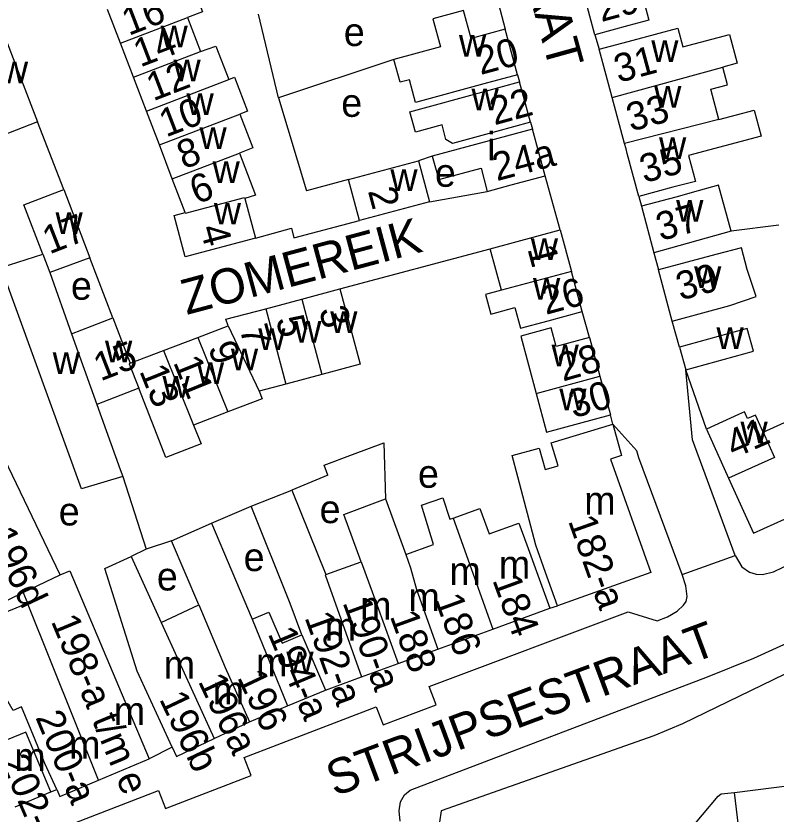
# Model space of a CAD drawing. Extents: x 159261 to 160849, y 382514 to 384534.
# Drawn here: x 159592.3 to 159700.2, y 383560.8 to 383674.1 of the extents above; entities that cross this region are included whole.
import ezdxf

# ---------------------------------------------------------------- set-up
doc = ezdxf.new("R2010")
doc.units = 0
for name, color, linetype in [('BLT_Basislijn', 7, 'Continuous'), ('BLT_Bebouwing', 7, 'Continuous'), ('BLT_Centroide', 7, 'Continuous'), ('BLT_Huisnummer', 7, 'Continuous'), ('BLT_Huisnummer_ tussenligend', 7, 'Continuous'), ('BLT_Huisnummer_reeks', 7, 'Continuous'), ('BLT_Onderverdeling_panden', 7, 'Continuous'), ('BLT_Straatnaam', 7, 'Continuous'), ('BLT_Vlakafsluiter', 7, 'Continuous')]:
    doc.layers.add(name, color=color, linetype=linetype)

msp = doc.modelspace()

# ---------------------------------------------------------------- linework, layer by layer
at = {"layer": 'BLT_Basislijn'}
for p, q in [((159659.71, 383679.86), (159661.77, 383672.22)), ((159629.57, 383662.47), (159626.72, 383674.34)), ((159674.5, 383671.45), (159675.09, 383669.38)), ((159645.96, 383667.92), (159629.57, 383662.47)), ((159663.52, 383665.76), (159663.8, 383664.74)), ((159629.57, 383662.47), (159633.56, 383649.28)), ((159599.11, 383649.46), (159595.35, 383659.06)), ((159665.36, 383659.02), (159665.63, 383658.01)), ((159651.37, 383654.2), (159649.46, 383653.52)), ((159669.57, 383643.73), (159667.42, 383651.42)), ((159639.52, 383650.87), (159633.56, 383649.28)), ((159651.02, 383647.73), (159659.22, 383649.2)), ((159680.74, 383648.49), (159681.13, 383647.09)), ((159700.59, 383644.39), (159693.83, 383643.55)), ((159638.3, 383635.36), (159659.63, 383641.06)), ((159682.88, 383640.47), (159683.52, 383638.07)), ((159606.05, 383631.24), (159602.8, 383639.76)), ((159673.73, 383628.43), (159672.7, 383632.15)), ((159686.51, 383627.1), (159685.45, 383630.78)), ((159690.33, 383615.44), (159687.4, 383623.88)), ((159677.06, 383616.13), (159676.69, 383617.47)), ((159607.46, 383608.7), (159610.77, 383598.38)), ((159636.57, 383608.92), (159631.46, 383606.79)), ((159620.04, 383602.07), (159625.7, 383604.48)), ((159614.37, 383599.57), (159610.77, 383598.38)), ((159668.08, 383590), (159669.16, 383590.36)), ((159614.49, 383570.27), (159611.2, 383568.62)), ((159694.31, 383563.86), (159732.25, 383568.6)), ((159694.87, 383559.09), (159694.31, 383563.86))]:
    msp.add_line(p, q, dxfattribs=at)
for points in [[(159626.29, 383642.57), (159631.42, 383643.96), (159631.77, 383642.61), (159641.07, 383645.08)], [(159694.42, 383597.5), (159695.36, 383595.88), (159696.43, 383595.15), (159697.4, 383594.83), (159698.31, 383594.8), (159699.85, 383595.18), (159703.97, 383597.18), (159705.93, 383600.96), (159728.05, 383611.8), (159729.24, 383609.4), (159734.22, 383611.81), (159733.05, 383614.23), (159738.78, 383617.01), (159744.28, 383619.48), (159755.69, 383623.79), (159759.97, 383622.49), (159761.42, 383623.03), (159762.55, 383623.97), (159762.98, 383625.2), (159761.06, 383634.82)], [(159694.42, 383597.5), (159688.33, 383613.92), (159687.4, 383623.88)], [(159686.89, 383594.79), (159680.75, 383611.36), (159680.44, 383612.37), (159677.06, 383616.13)], [(159640.1, 383611.84), (159644.54, 383613.5), (159644.75, 383605.52)], [(159636.57, 383608.92), (159636.05, 383610.32), (159640.1, 383611.84)], [(159610.77, 383598.38), (159608.66, 383597.35)], [(159572.03, 383548.44), (159612.55, 383564.12), (159613.53, 383561.58), (159625.68, 383566.28), (159624.71, 383568.8), (159643.44, 383575.99), (159644.45, 383573.43), (159651.96, 383576.3), (159650.97, 383578.9), (159679.2, 383589.51), (159683.32, 383588.24), (159684.78, 383588.8), (159686.16, 383589.57), (159687.09, 383590.43), (159687.44, 383590.96), (159687.57, 383591.66), (159687.41, 383593.17), (159686.89, 383594.79)], [(159646.83, 383559.78), (159646.69, 383561.24), (159646.89, 383562.53), (159647.47, 383563.51), (159648.25, 383564.18), (159690.48, 383580.27), (159697.07, 383582.94), (159703.49, 383585.83), (159705.74, 383586.92), (159707.76, 383587.49), (159709.49, 383587.56), (159710.32, 383587.45), (159711.21, 383587.05), (159712.09, 383586.63), (159712.67, 383586.07)], [(159712.67, 383586.07), (159686.93, 383573.58), (159682.84, 383571.9), (159652.65, 383561.22), (159652.2, 383558.02), (159651.56, 383556.45), (159648.16, 383555.44)], [(159684.97, 383522.85), (159684.72, 383523.68), (159681.3, 383538.66), (159680.75, 383544.01), (159681.55, 383548.59), (159683.13, 383552.24), (159685.3, 383555.37), (159691.98, 383563.32), (159692.44, 383563.65), (159694.31, 383563.86)]]:
    msp.add_lwpolyline(points, dxfattribs=at)
at = {"layer": 'BLT_Bebouwing'}
for p, q in [((159674.5, 383671.45), (159672.75, 383677.95)), ((159663.52, 383665.76), (159661.77, 383672.22)), ((159676.95, 383662.55), (159675.09, 383669.38)), ((159665.36, 383659.02), (159663.8, 383664.74)), ((159678.7, 383656), (159676.95, 383662.55)), ((159667.42, 383651.42), (159665.63, 383658.01)), ((159614.49, 383650.98), (159612.67, 383655.8)), ((159616.32, 383646.21), (159614.49, 383650.98)), ((159681.13, 383647.09), (159682.88, 383640.47)), ((159693.83, 383643.55), (159682.88, 383640.47)), ((159672.7, 383632.15), (159671.15, 383637.84)), ((159685.45, 383630.78), (159683.52, 383638.07)), ((159597.12, 383637.69), (159600.18, 383628.98)), ((159673.73, 383628.43), (159675.21, 383622.95)), ((159686.51, 383627.1), (159687.4, 383623.88)), ((159675.21, 383622.95), (159676.69, 383617.47)), ((159603.79, 383618.93), (159607.11, 383609.72)), ((159622.38, 383617.88), (159617.52, 383616.01)), ((159698.36, 383615.02), (159703.99, 383617.56)), ((159690.33, 383615.44), (159693.47, 383608.49)), ((159676.72, 383611.16), (159682.43, 383595.08)), ((159693.47, 383608.49), (159696.99, 383600.69)), ((159625.7, 383604.48), (159631.46, 383606.79)), ((159631.46, 383606.79), (159636.28, 383594.79)), ((159696.99, 383600.69), (159709.14, 383606.15)), ((159638.84, 383603.31), (159644.75, 383605.52)), ((159644.75, 383605.52), (159647.63, 383597.62)), ((159641.31, 383596.62), (159638.84, 383603.31)), ((159614.37, 383599.57), (159620.04, 383602.07)), ((159618.24, 383590.49), (159614.37, 383599.57)), ((159608.66, 383597.35), (159612.92, 383587.97)), ((159636.28, 383594.79), (159641.31, 383596.62)), ((159682.43, 383595.08), (159669.16, 383590.36)), ((159585.94, 383588.7), (159593.34, 383592.23)), ((159585.13, 383587.11), (159593.93, 383590.75)), ((159612.92, 383587.97), (159618.24, 383590.49)), ((159660.01, 383587.05), (159668.08, 383590)), ((159652.2, 383584.2), (159660.01, 383587.05)), ((159646.58, 383582.16), (159652.2, 383584.2)), ((159641.36, 383580.25), (159646.58, 383582.16)), ((159636.25, 383578.39), (159641.36, 383580.25)), ((159630.84, 383576.14), (159636.25, 383578.39)), ((159625.47, 383573.88), (159630.84, 383576.14)), ((159604.02, 383565.6), (159611.2, 383568.62)), ((159597.25, 383563.92), (159598.11, 383564.28)), ((159592.17, 383561.79), (159597.25, 383563.92))]:
    msp.add_line(p, q, dxfattribs=at)
for points in [[(159672.75, 383677.95), (159677.58, 383679.25), (159680.41, 383680.01), (159686.05, 383681.52), (159687.12, 383677.53), (159681.47, 383676.01), (159682.14, 383673.51), (159679.33, 383672.75), (159674.5, 383671.45)], [(159616.94, 383679.5), (159618.79, 383674.7), (159616.65, 383673.88)], [(159607.13, 383670.22), (159605.28, 383675.03)], [(159661.77, 383672.22), (159656.94, 383670.91), (159655.85, 383674.89), (159651.49, 383673.72), (159652.56, 383669.71), (159645.96, 383667.92)], [(159616.65, 383673.88), (159618.5, 383669.07)], [(159584.97, 383670.03), (159590.33, 383672.13), (159595.35, 383659.06)], [(159675.09, 383669.38), (159679.92, 383670.68), (159686.25, 383672.39), (159686.97, 383669.71), (159693.58, 383671.49), (159694.69, 383667.39), (159692.64, 383666.83)], [(159608.98, 383665.41), (159607.13, 383670.22)], [(159618.5, 383669.07), (159620.67, 383669.81), (159622.5, 383665.09)], [(159663.52, 383665.76), (159658.7, 383664.45), (159649.04, 383661.83), (159648.16, 383665.06), (159646.83, 383664.7), (159645.96, 383667.92)], [(159692.1, 383659.4), (159690.94, 383663.69), (159693.32, 383664.33), (159692.64, 383666.83)], [(159610.82, 383660.6), (159608.98, 383665.41)], [(159622.5, 383665.09), (159623.31, 383665.4), (159625.16, 383660.59), (159624.09, 383660.18)], [(159653.35, 383656.58), (159652.79, 383658.65), (159649, 383657.62), (159648.21, 383660.5), (159658.98, 383663.43), (159663.8, 383664.74)], [(159612.67, 383655.8), (159610.82, 383660.6)], [(159692.1, 383659.4), (159697.12, 383660.74), (159698.11, 383657.05), (159687.78, 383654.27), (159688.76, 383650.62), (159685.57, 383649.78), (159680.74, 383648.49)], [(159624.09, 383660.18), (159625.93, 383655.37), (159624.04, 383654.64)], [(159595.35, 383659.07), (159595.35, 383659.06), (159590.13, 383657.06)], [(159665.36, 383659.02), (159660.53, 383657.71), (159654.26, 383656), (159653.35, 383656.58)], [(159665.63, 383658.01), (159651.37, 383654.2)], [(159680.74, 383648.49), (159679.08, 383654.6), (159678.91, 383655.25), (159678.7, 383656)], [(159624.04, 383654.64), (159626.29, 383648.68), (159624.78, 383648.21)], [(159651.37, 383654.2), (159652.34, 383650.88), (159658.33, 383652.51), (159659.22, 383649.2)], [(159639.52, 383650.87), (159649.46, 383653.52)], [(159649.46, 383653.52), (159651.02, 383647.73)], [(159659.22, 383649.2), (159662.6, 383650.11), (159667.42, 383651.42)], [(159641.07, 383645.08), (159639.52, 383650.87)], [(159596.11, 383640.3), (159593.39, 383647.29), (159599.11, 383649.46)], [(159599.11, 383649.46), (159602.8, 383639.76)], [(159693.83, 383643.55), (159692.06, 383650.06), (159689.16, 383649.28), (159685.96, 383648.4), (159681.13, 383647.09)], [(159624.78, 383648.21), (159626.29, 383642.57)], [(159651.02, 383647.73), (159641.07, 383645.08)], [(159626.29, 383642.57), (159616.33, 383639.89), (159614.76, 383645.79), (159616.32, 383646.21)], [(159659.63, 383641.06), (159669.57, 383643.73)], [(159669.57, 383643.73), (159671.16, 383637.84), (159671.15, 383637.84)], [(159685.45, 383630.78), (159693.64, 383633), (159697.39, 383634.25), (159696.13, 383638.12), (159695.32, 383641.19), (159691.65, 383640.22), (159683.52, 383638.07)], [(159590.2, 383638.41), (159596.11, 383640.3)], [(159661.21, 383635.17), (159659.63, 383641.06)], [(159602.8, 383639.76), (159597.12, 383637.69)], [(159607.46, 383608.7), (159601.59, 383606.96), (159590.2, 383638.41)], [(159632.87, 383633.91), (159638.3, 383635.36)], [(159638.3, 383635.36), (159639.79, 383629.78), (159641.18, 383624.67), (159635.74, 383623.2)], [(159661.21, 383635.17), (159658.95, 383634.55)], [(159658.95, 383634.55), (159659.71, 383631.78), (159663.12, 383632.71), (159663.92, 383629.77), (159667.87, 383630.84), (159672.7, 383632.15)], [(159627.76, 383632.54), (159632.87, 383633.91)], [(159622.44, 383630.13), (159622.11, 383631.03), (159627.76, 383632.54)], [(159600.18, 383628.98), (159606.05, 383631.24)], [(159606.05, 383631.24), (159608.53, 383624.79)], [(159618.1, 383628.46), (159622.44, 383630.13)], [(159673.73, 383628.43), (159669.01, 383627.15), (159668.29, 383629.8), (159663.97, 383628.63), (159666.17, 383620.51)], [(159687.4, 383623.88), (159696.99, 383626.51), (159696.11, 383629.73), (159686.51, 383627.1)], [(159613.24, 383626.6), (159618.1, 383628.46)], [(159608.53, 383624.79), (159613.24, 383626.6)], [(159635.74, 383623.2), (159630.63, 383621.83)], [(159609.74, 383621.25), (159603.79, 383618.93)], [(159617.52, 383616.01), (159618.59, 383613.35), (159613.59, 383611.4), (159612.68, 383613.72), (159609.74, 383621.25)], [(159626.82, 383620.81), (159627.23, 383619.74), (159622.38, 383617.88)], [(159630.63, 383621.83), (159626.82, 383620.81)], [(159666.17, 383620.51), (159667.64, 383615.03), (159676.69, 383617.47)], [(159698.36, 383615.02), (159697.28, 383617.41), (159696.17, 383616.94), (159695.75, 383617.89), (159694.89, 383617.5), (159690.33, 383615.44)], [(159663.55, 383608.68), (159662.73, 383611.71), (159666.6, 383612.75), (159667.42, 383609.72), (159669.27, 383610.22), (159668.29, 383613.48), (159677.06, 383616.13)], [(159677.06, 383616.13), (159678.26, 383611.7)], [(159598.58, 383594.73), (159590.11, 383612.4)], [(159678.26, 383611.7), (159676.72, 383611.16)], [(159607.11, 383609.72), (159607.46, 383608.7)], [(159669.16, 383590.36), (159667.48, 383595.08), (159666.1, 383598.98), (159663.55, 383608.68)], [(159647.63, 383597.62), (159651.58, 383599.05), (159649.88, 383604.64), (159652.89, 383605.67), (159653.89, 383602.64), (159654.39, 383602.82)], [(159632.87, 383586.23), (159631.24, 383590.69), (159625.7, 383604.48)], [(159654.39, 383602.82), (159658.14, 383604.19), (159659.46, 383600.55), (159663.67, 383602.09), (159664.81, 383598.99), (159666.37, 383594.69), (159668.08, 383590)], [(159620.04, 383602.07), (159625.84, 383588.47)], [(159604.89, 383595.65), (159608.66, 383597.35)], [(159598.58, 383594.73), (159599.93, 383595.3), (159611.2, 383568.62)], [(159614.49, 383570.27), (159609.51, 383581.07), (159604.89, 383595.65)], [(159593.34, 383592.23), (159593.93, 383590.75)], [(159625.84, 383588.47), (159628.22, 383589.47), (159630.08, 383585.06), (159632.87, 383586.23)], [(159620.44, 383571.49), (159625.47, 383573.88)], [(159614.49, 383570.27), (159615.09, 383568.96), (159620.44, 383571.49)], [(159598.11, 383564.28), (159598.54, 383563.29), (159604.02, 383565.6)]]:
    msp.add_lwpolyline(points, dxfattribs=at)
at = {"layer": 'BLT_Onderverdeling_panden'}
for p, q in [((159607.13, 383670.22), (159616.65, 383673.88)), ((159608.98, 383665.41), (159618.5, 383669.07)), ((159676.95, 383662.55), (159692.64, 383666.83)), ((159610.82, 383660.6), (159622.5, 383665.09)), ((159612.67, 383655.8), (159624.09, 383660.18)), ((159692.1, 383659.4), (159678.7, 383656)), ((159614.49, 383650.98), (159624.04, 383654.64)), ((159596.11, 383640.3), (159597.12, 383637.69)), ((159671.16, 383637.84), (159661.21, 383635.17)), ((159632.87, 383633.91), (159635.74, 383623.2)), ((159627.76, 383632.54), (159630.63, 383621.83)), ((159622.44, 383630.13), (159626.82, 383620.81)), ((159600.18, 383628.98), (159603.79, 383618.93)), ((159618.1, 383628.46), (159622.38, 383617.88)), ((159613.24, 383626.6), (159617.52, 383616.01)), ((159666.17, 383620.51), (159675.21, 383622.95)), ((159654.39, 383602.82), (159660.01, 383587.05)), ((159641.31, 383596.62), (159643.58, 383590.4)), ((159593.34, 383592.23), (159598.58, 383594.73)), ((159604.02, 383565.6), (159593.93, 383590.75)), ((159618.24, 383590.49), (159622, 383581.6)), ((159643.58, 383590.4), (159646.58, 383582.16)), ((159612.92, 383587.97), (159620.44, 383571.49)), ((159625.84, 383588.47), (159630.84, 383576.14)), ((159632.87, 383586.23), (159636.25, 383578.39)), ((159622, 383581.6), (159625.47, 383573.88)), ((159597.25, 383563.92), (159593.69, 383572.41))]:
    msp.add_line(p, q, dxfattribs=at)
for points in [[(159616.32, 383646.21), (159616.38, 383646.09), (159624.74, 383648.34), (159624.78, 383648.21)], [(159608.53, 383624.79), (159608.38, 383624.73), (159609.74, 383621.25)], [(159698.36, 383615.02), (159699.98, 383611.42), (159693.47, 383608.49)], [(159647.63, 383597.62), (159648.31, 383595.76), (159649.17, 383592.66), (159652.2, 383584.2)], [(159636.28, 383594.79), (159636.18, 383594.75), (159641.36, 383580.25)], [(159598.11, 383564.28), (159596.4, 383567.96), (159595.01, 383571.31), (159593.06, 383576.01), (159591.89, 383575.51), (159585.13, 383587.11)], [(159593.69, 383572.41), (159591.05, 383571.34), (159589.62, 383574.69), (159587.14, 383573.63)]]:
    msp.add_lwpolyline(points, dxfattribs=at)
at = {"layer": 'BLT_Vlakafsluiter'}
msp.add_line((159686.89, 383594.79), (159694.42, 383597.5), dxfattribs=at)

# ---------------------------------------------------------------- texts
at = {"layer": 'BLT_Centroide'}
for s, p in [('e', (159638.84, 383669.84)), ('w', (159612.82, 383669.66)), ('w', (159655.19, 383668.34)), ('w', (159682.49, 383667.59)), ('w', (159590.16, 383664.56)), ('w', (159614.66, 383664.84)), ('w', (159656.97, 383660.72)), ('w', (159682.91, 383661.09)), ('w', (159616.51, 383660.03)), ('e', (159638.48, 383659.78)), ('w', (159618.35, 383655.22)), ('i', (159659.19, 383653.59)), ('w', (159683.6, 383653.78)), ('w', (159620.21, 383650.38)), ('e', (159651.78, 383649.85)), ('w', (159645.45, 383649.25)), ('w', (159686.03, 383644.88)), ('w', (159620.39, 383644.5)), ('w', (159597.91, 383643.16)), ('w', (159665.39, 383639.44)), ('w', (159688.58, 383635.5)), ('e', (159600.1, 383633.81)), ('w', (159665.7, 383633.81)), ('w', (159636.91, 383629.09)), ('w', (159631.8, 383627.72)), ('w', (159691.75, 383626.81)), ('w', (159626.69, 383626.67)), ('w', (159604.94, 383624.91)), ('w', (159622.81, 383623.78)), ('w', (159668.34, 383624.35)), ('w', (159597.51, 383623.28)), ('w', (159617.98, 383621.84)), ('w', (159613.09, 383619.91)), ('w', (159669.44, 383618.12)), ('w', (159695.16, 383613.44)), ('e', (159649.37, 383607.11)), ('m', (159672.98, 383603.31)), ('e', (159598.37, 383601.76)), ('e', (159635.41, 383602.09)), ('e', (159624.62, 383595.28)), ('m', (159660.86, 383594.22)), ('m', (159653.84, 383593.3)), ('e', (159612.3, 383592.53)), ('m', (159648.03, 383589.61)), ('m', (159641.16, 383588.38)), ('m', (159636.12, 383585.41)), ('m', (159626.38, 383580.36)), ('w', (159630.69, 383580.78)), ('m', (159613.27, 383580)), ('m', (159620.22, 383576.36)), ('m', (159606.19, 383573.44)), ('m', (159599.84, 383568.64)), ('m', (159592.06, 383566.92))]:
    msp.add_text(s, height=4, dxfattribs=at).set_placement(p)
at = {"layer": 'BLT_Huisnummer'}
for s, rotation, p in [('14', 21.0019, (159609.94, 383666.78)), ('20', 15.1898, (159658.25, 383665.71)), ('22', 15.2008, (159660.22, 383658.57)), ('33', 15.223, (159679.6, 383657.67)), ('10', 21.0019, (159613.59, 383656.84)), ('24a', 14.9979, (159660.56, 383650.63)), ('6', 21.0019, (159617.93, 383647.33)), ('2', 285.029, (159642.24, 383649.27)), ('37', 15.3536, (159683.81, 383642.13)), ('17', 21.3263, (159597.05, 383640.23)), ('4', 285.029, (159618.39, 383643.99)), ('1', 285.029, (159664.89, 383641.05)), ('39', 15.344, (159686.64, 383633.68)), ('26', 15.1967, (159667.52, 383631.65)), ('3', 285.029, (159635.29, 383632.37)), ('7', 285.029, (159624.02, 383629.73)), ('15', 21.3302, (159604.3, 383622.2)), ('9', 292.003, (159619.5, 383626.99)), ('28', 16.0593, (159669.95, 383622.18)), ('13', 292.003, (159609.77, 383623.71)), ('30', 16.0593, (159671.45, 383616.96)), ('41', 23.3536, (159694.2, 383611.25)), ('196d', 295.1981, (159588.22, 383600.47)), ('184', 290.0347, (159659.9, 383594.03)), ('186', 290.0257, (159651.7, 383591.29)), ('196', 295.3192, (159623.65, 383580.22)), ('196a', 295.3161, (159618.09, 383579.65)), ('196b', 295.3192, (159612.58, 383577.13))]:
    msp.add_text(s, height=4, rotation=rotation, dxfattribs=at).set_placement(p)
at = {"layer": 'BLT_Huisnummer_ tussenligend'}
for s, rotation, p in [('29', 15.0561, (159675.4, 383673.23)), ('16', 21.0019, (159608.29, 383671.26)), ('31', 15.0561, (159677.83, 383664.59)), ('12', 21.0019, (159611.78, 383661.98)), ('8', 21.0019, (159616.12, 383652.3)), ('35', 15.223, (159681.48, 383650.36)), ('5', 285.029, (159629.16, 383631.04)), ('11', 292.003, (159614.58, 383624.95)), ('188', 290.0257, (159645.34, 383588.91))]:
    msp.add_text(s, height=4, rotation=rotation, dxfattribs=at).set_placement(p)
at = {"layer": 'BLT_Huisnummer_reeks'}
for s, rotation, p in [('182-a', 289.5466, (159670.65, 383602.43)), ('190-a', 290.024, (159638.63, 383590.83)), ('192-a', 290.0257, (159633.23, 383588.72)), ('198-a t/m e', 292.5291, (159597.22, 383588.18)), ('194-a', 292.8232, (159628.01, 383586.42)), ('200-a', 292.5291, (159595.01, 383574.53)), ('202-a', 293.3248, (159590.07, 383568.26))]:
    msp.add_text(s, height=4, rotation=rotation, dxfattribs=at).set_placement(p)
at = {"layer": 'BLT_Straatnaam'}
for s, rotation, p in [('DOELENSTRAAT', 285.4609, (159653.79, 383718.14)), ('ZOMEREIK', 15.0059, (159616.52, 383631.64)), ('STRIJPSESTRAAT', 20.4383, (159637.53, 383563.23))]:
    msp.add_text(s, height=5, rotation=rotation, dxfattribs=at).set_placement(p)

doc.saveas('drawing.dxf')
